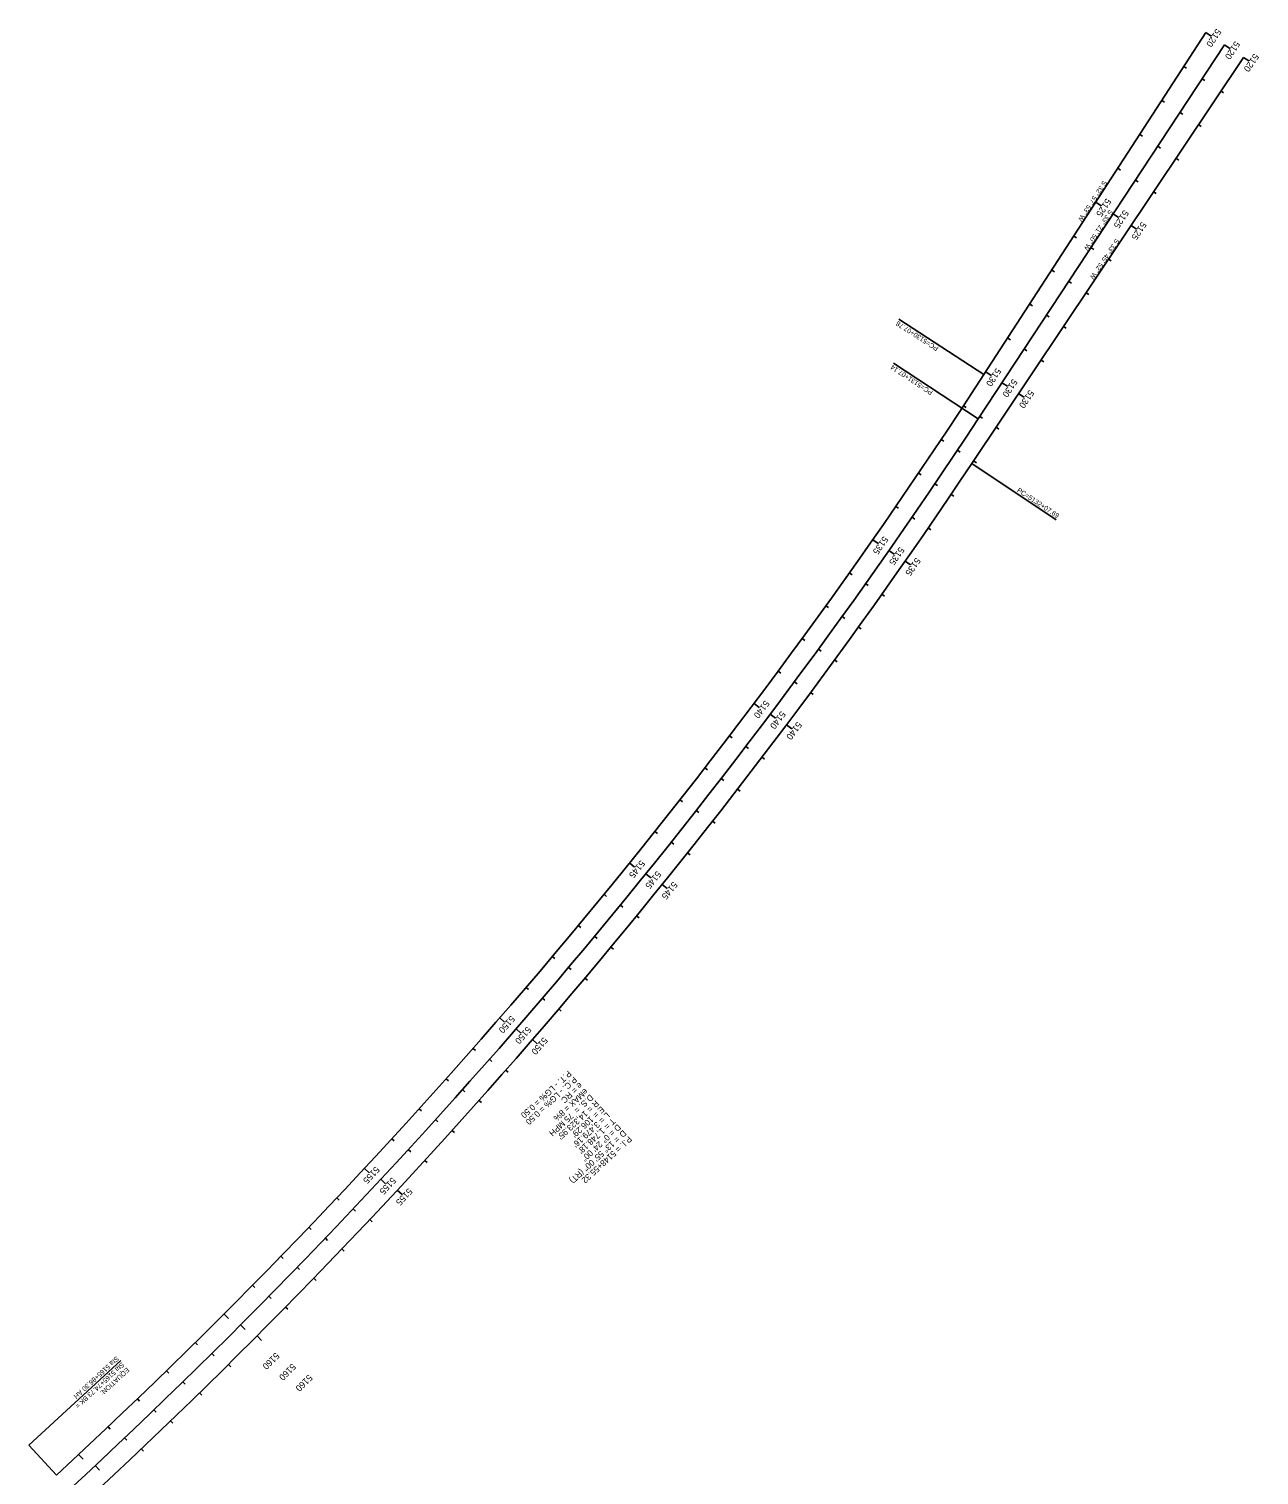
# Model space of a CAD drawing. Extents: x 2161211 to 2175594, y 601812 to 617732.
# Drawn here: x 2172554 to 2175594, y 614158 to 617732 of the extents above; entities that cross this region are included whole.
import ezdxf

# ---------------------------------------------------------------- set-up
doc = ezdxf.new("R2010")
doc.units = 0
for name, color, linetype in [('RD_HC_Cl', 7, 'Continuous'), ('RD_HC_Data', 7, 'Continuous'), ('RD_HC_Data_Tic', 7, 'Continuous'), ('RD_HC_TX_Sta50', 7, 'Continuous')]:
    doc.layers.add(name, color=color, linetype=linetype)

msp = doc.modelspace()

# ---------------------------------------------------------------- linework, layer by layer
at = {"layer": 'RD_HC_Cl'}
for p, q in [((2175462.5, 617723.5), (2174914.1, 616878)), ((2175508.7, 617693), (2174899.8, 616768.4)), ((2175555.6, 617662.2), (2174884.4, 616658.2))]:
    msp.add_line(p, q, dxfattribs=at)
for radius, end in [(14276, 327.03525), (14324, 326.63611), (14372, 326.23563)]:
    msp.add_arc((2162936.5, 624645.9), radius, 312.71947, end, dxfattribs=at)
at = {"layer": 'RD_HC_Data'}
for p, q in [((2174914.1, 616878), (2174703.5, 617014.6)), ((2174899.8, 616768.4), (2174690.3, 616906.3)), ((2174884.4, 616658.2), (2175093, 616518.7)), ((2172553.5, 614231.1), (2172780.3, 614440.5)), ((2172621.5, 614157.6), (2172553.5, 614231.1))]:
    msp.add_line(p, q, dxfattribs=at)
at = {"layer": 'RD_HC_Data_Tic'}
for p, q in [((2175462.5, 617723.5), (2175475.9, 617714.8)), ((2175508.7, 617693), (2175522.1, 617684.2)), ((2175408.1, 617639.6), (2175414.8, 617635.3)), ((2175555.6, 617662.2), (2175568.9, 617653.3)), ((2175453.7, 617609.5), (2175460.4, 617605.1)), ((2175500, 617579.1), (2175506.6, 617574.7)), ((2175353.7, 617555.7), (2175360.4, 617551.4)), ((2175398.7, 617526), (2175405.4, 617521.6)), ((2175444.4, 617496), (2175451.1, 617491.5)), ((2175299.2, 617471.8), (2175306, 617467.5)), ((2175343.7, 617442.5), (2175350.4, 617438.1)), ((2175244.8, 617387.9), (2175251.5, 617383.6)), ((2175388.8, 617412.8), (2175395.5, 617408.4)), ((2175288.7, 617359), (2175295.4, 617354.6)), ((2175333.3, 617329.7), (2175339.9, 617325.3)), ((2175190.4, 617304), (2175203.8, 617295.3)), ((2175233.7, 617275.4), (2175247.1, 617266.6)), ((2175277.7, 617246.6), (2175291, 617237.7)), ((2175136, 617220.1), (2175142.7, 617215.8)), ((2175178.7, 617191.9), (2175185.4, 617187.5)), ((2175222.1, 617163.4), (2175228.8, 617159)), ((2175081.6, 617136.2), (2175088.3, 617131.9)), ((2175123.7, 617108.4), (2175130.4, 617104)), ((2175166.5, 617080.3), (2175173.2, 617075.9)), ((2175027.2, 617052.3), (2175033.9, 617048)), ((2175068.7, 617024.9), (2175075.4, 617020.5)), ((2175110.9, 616997.2), (2175117.6, 616992.7)), ((2174972.8, 616968.4), (2174979.5, 616964.1)), ((2175013.7, 616941.4), (2175020.4, 616937)), ((2175055.4, 616914), (2175062, 616909.6)), ((2174918.4, 616884.5), (2174931.8, 616875.8)), ((2174958.7, 616857.8), (2174972.1, 616849)), ((2174999.8, 616830.9), (2175013.1, 616822)), ((2174863.7, 616800.8), (2174870.4, 616796.4)), ((2174903.7, 616774.3), (2174910.4, 616769.9)), ((2174944.2, 616747.8), (2174950.9, 616743.3)), ((2174808.5, 616717.4), (2174815.1, 616713)), ((2174848.5, 616691), (2174855.1, 616686.5)), ((2174888.6, 616664.6), (2174895.3, 616660.2)), ((2174752.6, 616634.5), (2174759.2, 616630)), ((2174792.7, 616608), (2174799.3, 616603.5)), ((2174832.8, 616581.7), (2174839.4, 616577.2)), ((2174696.2, 616551.9), (2174702.8, 616547.4)), ((2174736.3, 616525.4), (2174742.9, 616520.9)), ((2174776.4, 616499.1), (2174783, 616494.6)), ((2174639.2, 616469.7), (2174652.3, 616460.6)), ((2174679.3, 616443.2), (2174692.4, 616434.1)), ((2174581.7, 616387.9), (2174588.2, 616383.3)), ((2174719.4, 616416.9), (2174732.6, 616407.7)), ((2174621.7, 616361.5), (2174628.3, 616356.8)), ((2174661.9, 616335.1), (2174668.4, 616330.5)), ((2174523.5, 616306.6), (2174530, 616301.9)), ((2174563.6, 616280.1), (2174570.1, 616275.4)), ((2174603.8, 616253.7), (2174610.3, 616249.1)), ((2174464.8, 616225.6), (2174471.3, 616220.9)), ((2174504.9, 616199.1), (2174511.4, 616194.4)), ((2174545.1, 616172.8), (2174551.6, 616168)), ((2174405.6, 616145.1), (2174412, 616140.3)), ((2174445.7, 616118.6), (2174452.1, 616113.8)), ((2174345.8, 616064.9), (2174358.5, 616055.3)), ((2174485.9, 616092.2), (2174492.3, 616087.4)), ((2174385.9, 616038.4), (2174398.7, 616028.8)), ((2174426.1, 616012), (2174438.9, 616002.4)), ((2174285.4, 615985.2), (2174291.7, 615980.4)), ((2174325.5, 615958.7), (2174331.9, 615953.9)), ((2174365.7, 615932.3), (2174372.1, 615927.5)), ((2174224.4, 615906), (2174230.7, 615901.1)), ((2174264.6, 615879.4), (2174270.9, 615874.5)), ((2174304.8, 615853), (2174311.2, 615848.1)), ((2174162.9, 615827.1), (2174169.2, 615822.2)), ((2174203.1, 615800.5), (2174209.4, 615795.6)), ((2174100.9, 615748.7), (2174107.1, 615743.7)), ((2174243.4, 615774.1), (2174249.7, 615769.2)), ((2174141.1, 615722.1), (2174147.3, 615717.1)), ((2174181.4, 615695.7), (2174187.6, 615690.7)), ((2174038.3, 615670.7), (2174050.7, 615660.6)), ((2174078.5, 615644.1), (2174090.9, 615634)), ((2174118.8, 615617.6), (2174131.3, 615607.6)), ((2173975.1, 615593.2), (2173981.3, 615588.1)), ((2174015.4, 615566.5), (2174021.6, 615561.5)), ((2174055.7, 615540), (2174061.9, 615535)), ((2173911.5, 615516), (2173917.6, 615510.9)), ((2173951.7, 615489.4), (2173957.9, 615484.3)), ((2173992.1, 615462.9), (2173998.3, 615457.8)), ((2173847.2, 615439.4), (2173853.3, 615434.2)), ((2173887.5, 615412.7), (2173893.6, 615407.6)), ((2173927.9, 615386.2), (2173934.1, 615381)), ((2173782.5, 615363.2), (2173788.6, 615358)), ((2173822.8, 615336.5), (2173828.9, 615331.3)), ((2173717.2, 615287.5), (2173729.3, 615277)), ((2173863.2, 615309.9), (2173869.3, 615304.7)), ((2173757.5, 615260.7), (2173769.6, 615250.2)), ((2173651.4, 615212.2), (2173657.4, 615206.9)), ((2173798, 615234.1), (2173810.1, 615223.7)), ((2173691.8, 615185.4), (2173697.8, 615180.1)), ((2173585, 615137.3), (2173591, 615132)), ((2173732.3, 615158.8), (2173738.3, 615153.5)), ((2173625.5, 615110.6), (2173631.4, 615105.2)), ((2173666, 615083.9), (2173672, 615078.6)), ((2173518.2, 615063), (2173524.1, 615057.6)), ((2173558.6, 615036.2), (2173564.6, 615030.8)), ((2173599.2, 615009.5), (2173605.1, 615004.1)), ((2173450.8, 614989.1), (2173456.7, 614983.7)), ((2173491.3, 614962.2), (2173497.2, 614956.8)), ((2173531.9, 614935.5), (2173537.8, 614930.1)), ((2173382.9, 614915.7), (2173394.6, 614904.8)), ((2173423.4, 614888.8), (2173435.1, 614877.9)), ((2173464.1, 614862), (2173475.8, 614851.1)), ((2173314.5, 614842.8), (2173320.3, 614837.3)), ((2173355, 614815.8), (2173360.9, 614810.3)), ((2173395.8, 614789), (2173401.6, 614783.5)), ((2173245.5, 614770.3), (2173251.3, 614764.8)), ((2173286.2, 614743.3), (2173291.9, 614737.8)), ((2173326.9, 614716.5), (2173332.7, 614711)), ((2173176.1, 614698.3), (2173181.8, 614692.8)), ((2173216.8, 614671.3), (2173222.5, 614665.7)), ((2173257.6, 614644.4), (2173263.3, 614638.9)), ((2173106.2, 614626.8), (2173111.9, 614621.2)), ((2173146.9, 614599.8), (2173152.6, 614594.2)), ((2173187.7, 614572.9), (2173193.4, 614567.3)), ((2173035.7, 614555.9), (2173047.1, 614544.5)), ((2173076.5, 614528.8), (2173087.8, 614517.4)), ((2173117.4, 614501.8), (2173128.7, 614490.5)), ((2172964.8, 614485.4), (2172970.4, 614479.7)), ((2173005.6, 614458.2), (2173011.3, 614452.5)), ((2173046.6, 614431.2), (2173052.2, 614425.5)), ((2172893.4, 614415.4), (2172899, 614409.6)), ((2172934.3, 614388.2), (2172939.9, 614382.4)), ((2172975.3, 614361.1), (2172980.8, 614355.4)), ((2172821.5, 614345.9), (2172827, 614340.1)), ((2172862.4, 614318.6), (2172868, 614312.8)), ((2172903.5, 614291.5), (2172909, 614285.7)), ((2172749.1, 614276.9), (2172754.6, 614271.1)), ((2172790.1, 614249.6), (2172795.6, 614243.8)), ((2172676.2, 614208.4), (2172687.2, 614196.7)), ((2172831.2, 614222.4), (2172836.7, 614216.6)), ((2172717.3, 614181), (2172728.2, 614169.3))]:
    msp.add_line(p, q, dxfattribs=at)

# ---------------------------------------------------------------- texts
at = {"layer": 'RD_HC_Data'}
for s, height, rotation, p in [('S 32%%d 57\' 53" W', 12, 237.0352, (2175209.3, 617358.9)), ('S 33%%d 21\' 50" W', 12, 236.6361, (2175224.4, 617286.7)), ('S 33%%d 45\' 52" W', 12, 236.2356, (2175239.8, 617215.1)), ('PC=5130+07.78', 12, 147.0352, (2174802.9, 616945.4)), ('PC=5131+07.14', 12, 146.6361, (2174789, 616836.5)), ('PC=5132+07.69', 12, 326.2356, (2174994.7, 616589.3)), ('P.T. - LG% = 0.50', 15, 222.7195, (2173886.3, 615158.5)), ('P.C. - LG% = 0.50', 15, 222.7195, (2173899.9, 615143.8)), ('eMAX = 8%', 15, 222.7195, (2173927, 615114.4)), ('e = RC', 15, 222.7195, (2173913.5, 615129.1)), ('D.S. =  75 MPH', 15, 222.7195, (2173940.6, 615099.7)), ("R = 14,323.95'", 15, 222.7195, (2173954.2, 615085)), ("E = 106.29'", 15, 222.7195, (2173967.7, 615070.3)), ("L = 3,479.16'", 15, 222.7195, (2173981.3, 615055.6)), ("T = 1,748.18'", 15, 222.7195, (2173994.9, 615040.9)), ('    = 13° 55\' 00" (RT)', 15, 222.7195, (2174022, 615011.5)), ('P.I. = 5148+55.32', 15, 222.7195, (2174035.6, 614996.8)), ('D = 0° 24\' 00"', 15, 222.7195, (2174008.5, 615026.2)), ('D', 15, 222.7195, (2174022, 615011.5)), ('Sta 5165+86.30 AH', 12, 222.7195, (2172769.4, 614452.2)), ('Sta 5165+74.73 BK = ', 12, 222.7195, (2172783, 614437.5)), ('EQUATION:', 12, 222.7195, (2172795.2, 614424.3))]:
    msp.add_text(s, height=height, rotation=rotation, dxfattribs=at).set_placement(p)
at = {"layer": 'RD_HC_TX_Sta50'}
for s, rotation, p in [('5120', 237.0352, (2175488.6, 617734.4)), ('5120', 236.6361, (2175534.9, 617703.7)), ('5120', 236.2356, (2175581.8, 617672.8)), ('5125', 237.0352, (2175216.5, 617314.9)), ('5125', 236.6361, (2175259.9, 617286.1)), ('5125', 236.2356, (2175303.9, 617257)), ('5130', 237.0352, (2174944.5, 616895.4)), ('5130', 236.6361, (2174984.9, 616868.5)), ('5130', 236.2356, (2175026.1, 616841.4)), ('5135', 235.0597, (2174665.7, 616479.6)), ('5135', 235.0647, (2174705.7, 616453.2)), ('5135', 235.0703, (2174745.9, 616426.8)), ('5140', 233.053, (2174372.6, 616074)), ('5140', 233.0647, (2174412.7, 616047.5)), ('5140', 233.077, (2174452.9, 616021.1)), ('5145', 231.0463, (2174065.4, 615678.7)), ('5145', 231.0647, (2174105.6, 615652.1)), ('5145', 231.0836, (2174145.9, 615625.7)), ('5150', 229.0396, (2173744.6, 615294.6)), ('5150', 229.0647, (2173784.9, 615267.9)), ('5150', 229.0903, (2173825.4, 615241.3)), ('5155', 227.0328, (2173410.4, 614921.8)), ('5155', 227.0647, (2173451, 614894.9)), ('5155', 227.097, (2173491.6, 614868.2)), ('5160', 225.0261, (2173163.2, 614461.7)), ('5160', 225.0647, (2173203.9, 614434.6)), ('5160', 225.1037, (2173244.8, 614407.6))]:
    msp.add_text(s, height=16, rotation=rotation, dxfattribs=at).set_placement(p)

doc.saveas('drawing.dxf')
